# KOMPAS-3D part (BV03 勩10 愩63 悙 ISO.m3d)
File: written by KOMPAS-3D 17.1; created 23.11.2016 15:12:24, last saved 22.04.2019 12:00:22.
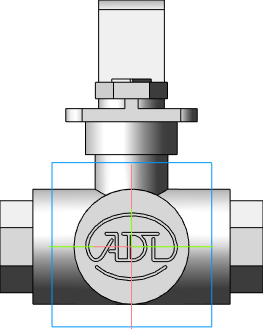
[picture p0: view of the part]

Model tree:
1. Операция без истории:2  (labels: Сталь 20  ГОСТ 1050-88)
